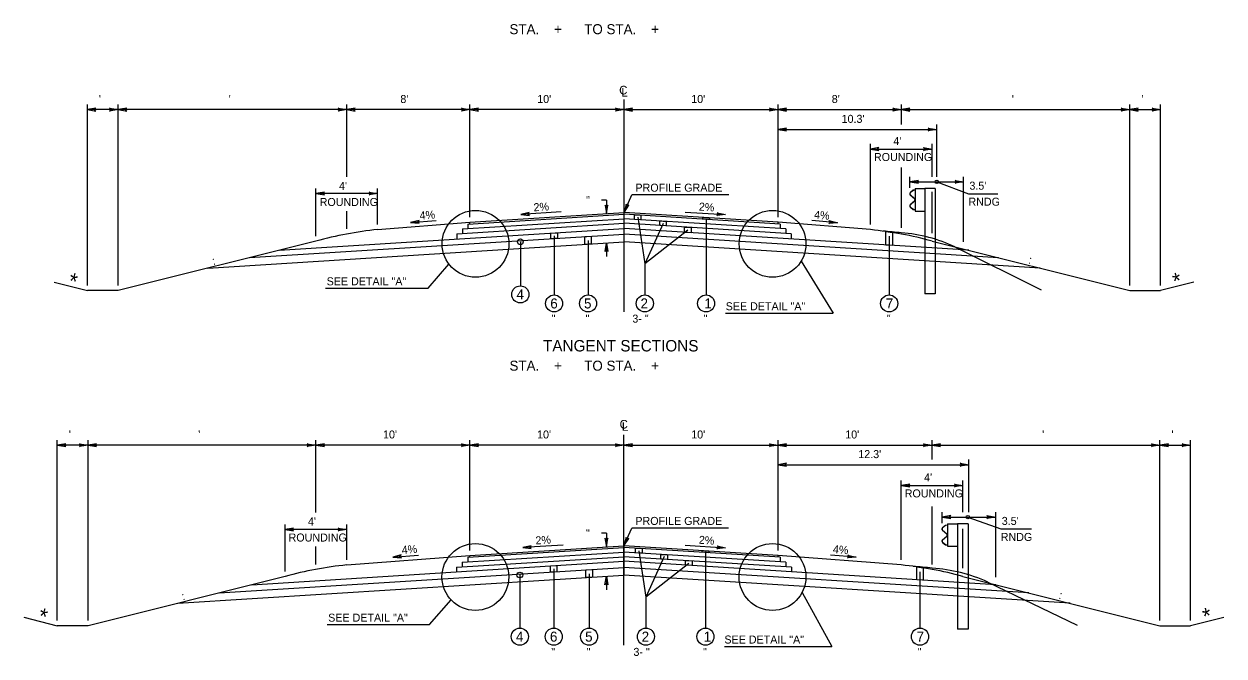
# Model space of a CAD drawing. Extents: x -540 to 1231, y -564 to 421.
# Drawn here: x -378.4 to -168.6, y -301.4 to -190.9 of the extents above; entities that cross this region are included whole.
import ezdxf

# ---------------------------------------------------------------- set-up
doc = ezdxf.new("R2010")
doc.units = 0
doc.layers.add('1', color=7, linetype='Continuous')
doc.layers.add('Des_ Drain_ Ftrs', color=7, linetype='Continuous')

msp = doc.modelspace()

# ---------------------------------------------------------------- linework, layer by layer
at = {"layer": '1'}
for p, q in [((-367.36, -236.6), (-367.36, -204.98)), ((-361.97, -236.6), (-361.97, -204.98)), ((-322, -217.64), (-322, -204.98)), ((-300.45, -224.66), (-300.45, -204.98)), ((-273.51, -241.23), (-273.51, -204.1)), ((-246.57, -224.66), (-246.57, -204.98)), ((-225.01, -208.45), (-225.01, -204.98)), ((-185.06, -236.61), (-185.06, -204.98)), ((-179.67, -236.61), (-179.67, -204.98)), ((-361.97, -205.86), (-367.36, -205.86)), ((-322, -205.86), (-361.97, -205.86)), ((-300.45, -205.86), (-322, -205.86)), ((-273.51, -205.86), (-300.45, -205.86)), ((-273.51, -205.86), (-246.57, -205.86)), ((-246.57, -205.86), (-225.01, -205.86)), ((-225.01, -205.86), (-185.06, -205.86)), ((-185.06, -205.86), (-179.67, -205.86)), ((-246.57, -209.33), (-218.82, -209.33)), ((-218.82, -217.61), (-218.82, -208.45)), ((-230.4, -225.96), (-230.4, -211.87)), ((-219.63, -217.61), (-219.63, -211.87)), ((-361.97, -233.49), (-361.97, -212.02)), ((-230.4, -212.75), (-219.63, -212.75)), ((-225.01, -226.52), (-225.01, -215.99)), ((-223.51, -219.56), (-223.51, -217.61)), ((-214.13, -228.97), (-214.13, -217.61)), ((-327.38, -227.96), (-327.38, -219.65)), ((-316.6, -225.95), (-316.6, -219.65)), ((-223.51, -218.49), (-214.13, -218.49)), ((-222.92, -219.95), (-223.43, -220.34)), ((-222.9, -219.98), (-223.42, -220.37)), ((-222.6, -219.9), (-222.92, -219.95)), ((-222.6, -219.93), (-222.9, -219.98)), ((-222.6, -219.67), (-222.6, -223.6)), ((-222.6, -219.67), (-220.92, -219.67)), ((-220.92, -219.67), (-220.92, -238.07)), ((-219.09, -219.67), (-220.92, -219.67)), ((-219.63, -227.48), (-219.63, -220.24)), ((-219.09, -219.67), (-219.09, -238.07)), ((-218.82, -218.49), (-213.26, -220.56)), ((-316.6, -220.53), (-327.38, -220.53)), ((-276.56, -221.67), (-277.44, -221.67)), ((-276.56, -221.67), (-276.56, -224.04)), ((-273.51, -223.84), (-272.12, -220.79)), ((-255.2, -220.79), (-272.12, -220.79)), ((-223.45, -220.78), (-222.72, -221.41)), ((-222.72, -221.86), (-223.45, -222.5)), ((-223.43, -220.75), (-222.7, -221.39)), ((-222.7, -221.88), (-223.43, -222.52)), ((-222.63, -221.6), (-222.63, -221.67)), ((-222.6, -221.6), (-222.6, -221.67)), ((-213.26, -220.56), (-208.11, -220.56)), ((-322, -226.73), (-322, -223.59)), ((-300.81, -225.86), (-273.51, -224.14)), ((-300.45, -225.53), (-273.51, -223.84)), ((-284.48, -223.76), (-291.56, -224.2)), ((-246.57, -225.54), (-273.51, -223.85)), ((-246.21, -225.86), (-273.51, -224.14)), ((-262.82, -223.78), (-255.75, -224.22)), ((-223.43, -222.93), (-222.92, -223.32)), ((-223.42, -222.91), (-222.9, -223.29)), ((-222.92, -223.32), (-222.6, -223.37)), ((-222.9, -223.29), (-222.6, -223.34)), ((-222.6, -223.6), (-220.92, -223.6)), ((-316.6, -226.83), (-300.45, -225.53)), ((-310.83, -225.61), (-306.34, -225.25)), ((-302.75, -227.57), (-273.51, -225.73)), ((-301.78, -226.71), (-273.51, -224.94)), ((-300.81, -225.86), (-300.81, -226.65)), ((-300.45, -225.83), (-300.45, -225.53)), ((-245.23, -226.72), (-273.51, -224.94)), ((-244.26, -227.58), (-273.51, -225.74)), ((-271.11, -224.65), (-269.87, -232.8)), ((-266.69, -225.79), (-269.87, -232.8)), ((-259.16, -224.94), (-259.16, -238.26)), ((-230.4, -226.84), (-246.57, -225.54)), ((-246.57, -225.84), (-246.57, -225.54)), ((-246.21, -225.86), (-246.21, -226.64)), ((-236.2, -225.63), (-240.69, -225.27)), ((-338.99, -231.74), (-273.51, -227.63)), ((-333.82, -230.45), (-273.51, -226.66)), ((-302.75, -227.57), (-302.75, -228.5)), ((-301.78, -226.71), (-301.78, -227.51)), ((-285.73, -227.9), (-285.73, -238.26)), ((-279.8, -228.73), (-279.8, -238.26)), ((-213.19, -230.46), (-273.51, -226.66)), ((-208.03, -231.75), (-273.51, -227.63)), ((-262.35, -226.91), (-269.87, -232.8)), ((-245.23, -226.72), (-245.23, -227.51)), ((-244.26, -227.58), (-244.26, -228.5)), ((-227.14, -228), (-227.14, -238.26)), ((-223.51, -227.62), (-223.51, -227.62)), ((-327.38, -228.84), (-361.97, -237.48)), ((-346.28, -233.56), (-273.51, -228.99)), ((-291.64, -228.96), (-291.64, -236.67)), ((-276.56, -229.19), (-276.56, -231.56)), ((-200.74, -233.57), (-273.51, -228.99)), ((-219.63, -228.85), (-185.06, -237.49)), ((-215.63, -229.85), (-200.58, -237.38)), ((-307.76, -237.08), (-304.12, -232.86)), ((-269.87, -232.8), (-269.87, -238.26)), ((-242.55, -232.36), (-236.96, -241.44)), ((-373.18, -236.02), (-367.36, -237.48)), ((-325.7, -237.08), (-307.76, -237.08)), ((-173.84, -236.03), (-179.67, -237.49)), ((-361.97, -237.48), (-367.36, -237.48)), ((-219.09, -238.07), (-220.92, -238.07)), ((-185.06, -237.49), (-179.67, -237.49)), ((-255.74, -241.44), (-236.96, -241.44)), ((-372.61, -295.19), (-372.61, -263.62)), ((-367.22, -295.19), (-367.22, -263.62)), ((-327.4, -276.28), (-327.4, -263.62)), ((-300.46, -282.91), (-300.46, -263.62)), ((-273.52, -299.47), (-273.52, -262.74)), ((-246.58, -282.91), (-246.58, -263.62)), ((-219.64, -267.05), (-219.64, -263.62)), ((-179.8, -295.19), (-179.8, -263.62)), ((-174.42, -295.19), (-174.42, -263.62)), ((-367.22, -264.5), (-372.61, -264.5)), ((-327.4, -264.5), (-367.22, -264.5)), ((-300.46, -264.5), (-327.4, -264.5)), ((-273.52, -264.5), (-300.46, -264.5)), ((-273.52, -264.5), (-246.58, -264.5)), ((-246.58, -264.5), (-219.64, -264.5)), ((-219.64, -264.5), (-179.8, -264.5)), ((-179.8, -264.5), (-174.42, -264.5)), ((-246.58, -267.93), (-213.21, -267.93)), ((-213.21, -276.21), (-213.21, -267.05)), ((-225.03, -284.58), (-225.03, -270.67)), ((-214.25, -276.21), (-214.25, -270.67)), ((-225.03, -271.55), (-214.25, -271.55)), ((-219.64, -285.35), (-219.64, -275.21)), ((-217.9, -278.16), (-217.9, -276.21)), ((-208.51, -287.57), (-208.51, -276.21)), ((-332.78, -286.58), (-332.78, -278.38)), ((-322, -284.57), (-322, -278.38)), ((-273.52, -282.09), (-272.13, -279.04)), ((-255.22, -279.04), (-272.13, -279.04)), ((-217.9, -277.09), (-208.51, -277.09)), ((-217.28, -278.55), (-217.82, -278.94)), ((-217.27, -278.58), (-217.8, -278.97)), ((-216.95, -278.5), (-217.28, -278.55)), ((-216.95, -278.53), (-217.27, -278.58)), ((-216.95, -278.27), (-216.95, -282.2)), ((-216.95, -278.27), (-215.2, -278.27)), ((-215.2, -278.27), (-215.2, -296.67)), ((-213.31, -278.27), (-215.2, -278.27)), ((-213.38, -277.09), (-207.62, -279.16)), ((-213.31, -278.27), (-213.31, -296.67)), ((-322, -279.26), (-332.78, -279.26)), ((-276.59, -279.92), (-277.47, -279.92)), ((-276.59, -279.92), (-276.59, -282.28)), ((-217.83, -279.37), (-217.07, -280.01)), ((-217.07, -280.46), (-217.83, -281.1)), ((-217.81, -279.35), (-217.05, -279.99)), ((-217.05, -280.48), (-217.81, -281.12)), ((-216.98, -280.2), (-216.98, -280.27)), ((-216.95, -280.2), (-216.95, -280.27)), ((-214.25, -286.03), (-214.25, -279.15)), ((-207.62, -279.16), (-202.27, -279.16)), ((-327.4, -285.35), (-327.4, -282.23)), ((-301.82, -284.98), (-273.52, -283.2)), ((-300.83, -284.11), (-273.52, -282.39)), ((-300.47, -283.79), (-273.52, -282.09)), ((-284.14, -281.99), (-291.22, -282.43)), ((-273.52, -282.09), (-273.52, -282.39)), ((-246.58, -283.79), (-273.52, -282.09)), ((-273.52, -282.39), (-273.52, -283.2)), ((-246.21, -284.11), (-273.52, -282.39)), ((-273.52, -283.2), (-273.52, -284.01)), ((-245.22, -284.98), (-273.52, -283.2)), ((-270.91, -282.97), (-269.68, -291.06)), ((-262.82, -282.01), (-255.75, -282.45)), ((-259.27, -283.17), (-259.27, -296.5)), ((-217.82, -281.53), (-217.28, -281.92)), ((-217.8, -281.5), (-217.27, -281.89)), ((-217.28, -281.92), (-216.95, -281.97)), ((-217.27, -281.89), (-216.95, -281.94)), ((-216.95, -282.2), (-215.2, -282.2)), ((-338.57, -288.91), (-273.52, -284.82)), ((-322, -285.45), (-300.47, -283.79)), ((-313.96, -284.07), (-309.47, -283.73)), ((-302.81, -285.85), (-273.52, -284.01)), ((-301.82, -284.98), (-301.82, -285.79)), ((-300.83, -284.11), (-300.83, -284.92)), ((-300.47, -284.09), (-300.47, -283.79)), ((-273.52, -284.01), (-273.52, -284.82)), ((-244.24, -285.85), (-273.52, -284.01)), ((-273.52, -284.82), (-273.52, -285.9)), ((-208.46, -288.91), (-273.52, -284.82)), ((-266.48, -284), (-269.68, -291.06)), ((-262.19, -285.2), (-269.68, -291.06)), ((-225.03, -285.46), (-246.58, -283.79)), ((-246.58, -284.09), (-246.58, -283.79)), ((-246.21, -284.11), (-246.21, -284.92)), ((-245.22, -284.98), (-245.22, -285.8)), ((-232.91, -284.08), (-237.39, -283.73)), ((-332.78, -287.46), (-367.22, -296.07)), ((-351.54, -292.15), (-273.52, -287.25)), ((-344.33, -290.35), (-273.52, -285.9)), ((-302.81, -285.85), (-302.81, -286.66)), ((-291.73, -287.21), (-291.73, -296.5)), ((-285.8, -286.16), (-285.8, -296.5)), ((-279.62, -287.01), (-279.62, -296.5)), ((-276.59, -287.44), (-276.59, -289.81)), ((-273.52, -285.9), (-273.52, -287.25)), ((-202.69, -290.35), (-273.52, -285.9)), ((-195.49, -292.15), (-273.52, -287.25)), ((-244.24, -285.85), (-244.24, -286.67)), ((-221.75, -286.63), (-221.75, -296.5)), ((-217.9, -286.22), (-217.9, -286.22)), ((-214.25, -287.46), (-179.8, -296.07)), ((-209.9, -288.45), (-194.28, -295.98)), ((-307.5, -295.88), (-303.76, -291.56)), ((-269.68, -291.06), (-269.68, -296.5)), ((-242.37, -290.27), (-237.17, -299.7)), ((-378.44, -294.61), (-372.61, -296.07)), ((-325.43, -295.88), (-307.5, -295.88)), ((-168.59, -294.62), (-174.42, -296.07)), ((-367.22, -296.07), (-372.61, -296.07)), ((-213.31, -296.67), (-215.2, -296.67)), ((-179.8, -296.07), (-174.42, -296.07)), ((-255.96, -299.7), (-237.17, -299.7))]:
    msp.add_line(p, q, dxfattribs=at)
for points in [[(-271.69, -224.26), (-270.54, -224.33), (-270.54, -225.13), (-271.69, -225.05)], [(-267.27, -225.33), (-266.12, -225.4), (-266.12, -226.2), (-267.27, -226.13)], [(-262.92, -226.4), (-261.78, -226.47), (-261.78, -227.4), (-262.92, -227.33)], [(-259.73, -224.71), (-258.58, -224.79), (-258.58, -225.08), (-259.73, -225.01)], [(-286.31, -227.47), (-285.16, -227.39), (-285.16, -228.36), (-286.31, -228.43)], [(-280.38, -228.06), (-279.23, -227.99), (-279.23, -229.35), (-280.38, -229.42)], [(-227.72, -227.17), (-226.57, -227.35), (-226.57, -229.62), (-227.72, -229.54)], [(-271.48, -282.52), (-270.34, -282.59), (-270.34, -283.4), (-271.48, -283.33)], [(-259.84, -282.95), (-258.7, -283.02), (-258.7, -283.32), (-259.84, -283.25)], [(-267.05, -283.61), (-265.9, -283.68), (-265.9, -284.49), (-267.05, -284.42)], [(-262.77, -284.69), (-261.62, -284.76), (-261.62, -285.57), (-262.77, -285.5)], [(-286.37, -285.63), (-285.23, -285.55), (-285.23, -286.63), (-286.37, -286.71)], [(-280.19, -286.32), (-279.04, -286.25), (-279.04, -287.59), (-280.19, -287.67)], [(-222.32, -285.79), (-221.17, -285.96), (-221.17, -288.11), (-222.32, -288.04)]]:
    msp.add_lwpolyline(points, close=True, dxfattribs=at)
for centre, radius in [((-218.82, -218.49), 0.3), ((-299.49, -229.32), 5.84), ((-247.53, -229.32), 5.84), ((-291.64, -228.96), 0.5), ((-291.64, -238.16), 1.49), ((-285.73, -239.74), 1.49), ((-279.8, -239.74), 1.49), ((-269.87, -239.74), 1.49), ((-259.16, -239.74), 1.49), ((-227.14, -239.74), 1.49), ((-299.5, -287.56), 5.84), ((-247.54, -287.56), 5.84), ((-291.73, -287.21), 0.5), ((-291.73, -297.99), 1.49), ((-285.8, -297.99), 1.49), ((-279.62, -297.99), 1.49), ((-269.68, -297.99), 1.49), ((-259.27, -297.99), 1.49), ((-221.75, -297.99), 1.49)]:
    msp.add_circle(centre, radius, dxfattribs=at)
for centre, radius, start, end in [((-223.27, -220.57), 0.278, 126.9799, 229.021), ((-223.27, -220.57), 0.249, 126.9799, 229.021), ((-222.88, -221.6), 0.249, 0, 49.0365), ((-222.88, -221.67), 0.249, 310.9635, 0), ((-222.88, -221.6), 0.278, 0, 49.0365), ((-222.88, -221.67), 0.278, 310.9635, 0), ((-223.27, -222.71), 0.278, 130.979, 233.0201), ((-223.27, -222.71), 0.249, 130.979, 233.0201), ((-309.72, -293.67), 67.19, 95.8795, 105.2381), ((-237.29, -293.68), 67.19, 74.7619, 84.1205), ((-235.84, -328.06), 101.24, 83.8633, 85.6775), ((-227.14, -254.68), 27.37, 65.1374, 85.5513), ((-315.12, -352.29), 67.19, 95.8795, 105.2381), ((-231.91, -352.29), 67.19, 74.7598, 84.1183)]:
    msp.add_arc(centre, radius, start, end, dxfattribs=at)
msp.add_ellipse((-213.38, -277.09), major_axis=(-0.311, 0), ratio=0.964041, dxfattribs=at)
for centre, major_axis, start_param, end_param in [((-217.64, -279.16), (-0.288, 0), 5.35781, 7.138763), ((-217.64, -279.16), (-0.258, 0), 5.35781, 7.138763), ((-217.64, -281.31), (-0.288, 0), 5.427608, 7.208561), ((-217.64, -281.31), (-0.258, 0), 5.427608, 7.208561), ((-217.24, -280.2), (0.258, 0), 0, 0.855848), ((-217.24, -280.27), (0.258, 0), 5.427337, 6.283185), ((-217.24, -280.2), (0.288, 0), 0, 0.855848), ((-217.24, -280.27), (0.288, 0), 5.427337, 6.283185), ((-230.86, -386.66), (105.02, 0), 1.463691, 1.495354), ((-221.83, -313.28), (28.39, 0), 1.136862, 1.493152)]:
    msp.add_ellipse(centre, major_axis=major_axis, ratio=0.964041, start_param=start_param, end_param=end_param, dxfattribs=at)
at = {"layer": 'Des_ Drain_ Ftrs'}
for points in [[(-367.36, -205.86), (-365.87, -206.11), (-366.16, -205.86), (-365.87, -205.62)], [(-361.97, -205.86), (-363.46, -206.11), (-363.16, -205.86), (-363.46, -205.62)], [(-361.97, -205.86), (-360.48, -206.11), (-360.77, -205.86), (-360.48, -205.62)], [(-322, -205.86), (-323.49, -206.11), (-323.2, -205.86), (-323.49, -205.62)], [(-322, -205.86), (-320.52, -206.11), (-320.81, -205.86), (-320.52, -205.62)], [(-300.45, -205.86), (-301.94, -206.11), (-301.64, -205.86), (-301.94, -205.62)], [(-300.45, -205.86), (-298.96, -206.11), (-299.26, -205.86), (-298.96, -205.62)], [(-273.51, -205.86), (-275, -206.11), (-274.7, -205.86), (-275, -205.62)], [(-273.51, -205.86), (-272.02, -206.11), (-272.32, -205.86), (-272.02, -205.62)], [(-246.57, -205.86), (-248.06, -206.11), (-247.76, -205.86), (-248.06, -205.62)], [(-246.57, -205.86), (-245.08, -206.11), (-245.37, -205.86), (-245.08, -205.62)], [(-225.01, -205.86), (-226.5, -206.11), (-226.21, -205.86), (-226.5, -205.62)], [(-225.01, -205.86), (-223.53, -206.11), (-223.82, -205.86), (-223.53, -205.62)], [(-185.06, -205.86), (-186.55, -206.11), (-186.25, -205.86), (-186.55, -205.62)], [(-185.06, -205.86), (-183.57, -206.11), (-183.86, -205.86), (-183.57, -205.62)], [(-179.67, -205.86), (-181.16, -206.11), (-180.86, -205.86), (-181.16, -205.62)], [(-246.57, -209.33), (-245.08, -209.58), (-245.38, -209.33), (-245.08, -209.08)], [(-218.82, -209.33), (-220.31, -209.58), (-220.02, -209.33), (-220.31, -209.08)], [(-230.4, -212.75), (-228.92, -213), (-229.21, -212.75), (-228.92, -212.5)], [(-219.63, -212.75), (-221.12, -213), (-220.82, -212.75), (-221.12, -212.5)], [(-223.51, -218.49), (-222.03, -218.73), (-222.32, -218.49), (-222.03, -218.24)], [(-214.13, -218.49), (-215.62, -218.73), (-215.32, -218.49), (-215.62, -218.24)], [(-327.38, -220.53), (-325.89, -220.78), (-326.19, -220.53), (-325.89, -220.28)], [(-316.6, -220.53), (-318.09, -220.78), (-317.8, -220.53), (-318.09, -220.28)], [(-273.51, -223.84), (-272.67, -222.59), (-273.02, -222.76), (-273.12, -222.39)], [(-291.56, -224.2), (-290.06, -224.36), (-290.37, -224.13), (-290.09, -223.86)], [(-276.56, -224.04), (-276.32, -222.55), (-276.56, -222.84), (-276.81, -222.55)], [(-255.75, -224.22), (-257.25, -224.38), (-256.94, -224.15), (-257.22, -223.88)], [(-310.83, -225.61), (-309.32, -225.74), (-309.64, -225.52), (-309.36, -225.25)], [(-236.2, -225.63), (-237.71, -225.76), (-237.39, -225.53), (-237.67, -225.26)], [(-276.56, -229.19), (-276.32, -230.68), (-276.56, -230.38), (-276.81, -230.68)], [(-372.61, -264.5), (-371.12, -264.75), (-371.42, -264.5), (-371.12, -264.26)], [(-367.22, -264.5), (-368.71, -264.75), (-368.41, -264.5), (-368.71, -264.26)], [(-367.22, -264.5), (-365.73, -264.75), (-366.03, -264.5), (-365.73, -264.26)], [(-327.4, -264.5), (-328.89, -264.75), (-328.6, -264.5), (-328.89, -264.26)], [(-327.4, -264.5), (-325.91, -264.75), (-326.21, -264.5), (-325.91, -264.26)], [(-300.46, -264.5), (-301.95, -264.75), (-301.65, -264.5), (-301.95, -264.26)], [(-300.46, -264.5), (-298.97, -264.75), (-299.27, -264.5), (-298.97, -264.26)], [(-273.52, -264.5), (-275.01, -264.75), (-274.71, -264.5), (-275.01, -264.26)], [(-273.52, -264.5), (-272.03, -264.75), (-272.33, -264.5), (-272.03, -264.26)], [(-246.58, -264.5), (-248.07, -264.75), (-247.77, -264.5), (-248.07, -264.26)], [(-246.58, -264.5), (-245.09, -264.75), (-245.39, -264.5), (-245.09, -264.26)], [(-219.64, -264.5), (-221.13, -264.75), (-220.83, -264.5), (-221.13, -264.26)], [(-219.64, -264.5), (-218.15, -264.75), (-218.44, -264.5), (-218.15, -264.26)], [(-179.8, -264.5), (-181.29, -264.75), (-181, -264.5), (-181.29, -264.26)], [(-179.8, -264.5), (-178.32, -264.75), (-178.61, -264.5), (-178.32, -264.26)], [(-174.42, -264.5), (-175.9, -264.75), (-175.61, -264.5), (-175.9, -264.26)], [(-246.58, -267.93), (-245.09, -268.18), (-245.38, -267.93), (-245.09, -267.68)], [(-213.21, -267.93), (-214.7, -268.18), (-214.4, -267.93), (-214.7, -267.68)], [(-225.03, -271.55), (-223.54, -271.8), (-223.83, -271.55), (-223.54, -271.31)], [(-214.25, -271.55), (-215.74, -271.8), (-215.44, -271.55), (-215.74, -271.31)], [(-217.9, -277.09), (-216.36, -277.33), (-216.66, -277.09), (-216.36, -276.84)], [(-208.51, -277.09), (-210.06, -277.33), (-209.75, -277.09), (-210.06, -276.84)], [(-332.78, -279.26), (-331.29, -279.51), (-331.59, -279.26), (-331.29, -279.01)], [(-322, -279.26), (-323.49, -279.51), (-323.2, -279.26), (-323.49, -279.01)], [(-276.59, -282.28), (-276.34, -280.8), (-276.59, -281.09), (-276.84, -280.8)], [(-273.52, -282.09), (-272.68, -280.84), (-273.03, -281.01), (-273.13, -280.63)], [(-291.22, -282.43), (-289.72, -282.59), (-290.03, -282.36), (-289.75, -282.09)], [(-255.75, -282.45), (-257.25, -282.61), (-256.94, -282.38), (-257.22, -282.11)], [(-313.96, -284.07), (-312.45, -284.21), (-312.77, -283.98), (-312.49, -283.71)], [(-232.91, -284.08), (-234.41, -284.22), (-234.1, -283.99), (-234.37, -283.72)], [(-276.59, -287.44), (-276.34, -288.93), (-276.59, -288.63), (-276.84, -288.93)]]:
    msp.add_lwpolyline(points, close=True, dxfattribs=at)

# ---------------------------------------------------------------- texts
at = {"layer": '1'}
for s, height, p in [('STA.    +      TO STA.    +     ', 1.75, (-293.54, -192.68)), (" '", 1.4, (-365.86, -204.71)), ("  '", 1.4, (-343.68, -204.71)), ("8'", 1.4, (-312.62, -204.71)), ("10'", 1.4, (-288.69, -204.71)), ("10'", 1.4, (-261.75, -204.71)), ("8'", 1.4, (-237.18, -204.71)), ("  '", 1.4, (-206.73, -204.71)), (" '", 1.4, (-183.56, -204.71)), ("10.3'", 1.4, (-235.46, -208.18)), ("4'", 1.4, (-226.41, -212.05)), ('ROUNDING', 1.4, (-229.8, -214.85)), ("4'", 1.4, (-323.35, -219.91)), ('PROFILE GRADE', 1.4, (-271.51, -220.21)), ("3.5'", 1.4, (-213.11, -219.86)), ('ROUNDING', 1.4, (-326.73, -222.71)), ('RNDG', 1.4, (-213.28, -222.66)), ('SEE DETAIL "A"', 1.4, (-325.51, -236.58)), ('4', 1.75, (-292.31, -239.03)), ('6', 1.75, (-286.4, -240.62)), ('5', 1.75, (-280.5, -240.62)), ('2', 1.75, (-270.62, -240.62)), ('1', 1.75, (-259.46, -240.62)), ('7', 1.75, (-227.73, -240.62)), ('SEE DETAIL "A"', 1.4, (-255.73, -240.94)), (' "', 1.4, (-286.68, -243.1)), (' "', 1.4, (-280.75, -243.1)), ('3- "', 1.4, (-272.05, -243.1)), (' "', 1.4, (-260.1, -243.1)), ('  "', 1.4, (-228.59, -243.1)), ('TANGENT SECTIONS', 2, (-287.68, -248.14)), ('STA.    +      TO STA.    +     ', 1.75, (-293.54, -251.5)), (" '", 1.4, (-371.11, -263.35)), ("  '", 1.4, (-349.01, -263.35)), ("10'", 1.4, (-315.65, -263.35)), ("10'", 1.4, (-288.71, -263.35)), ("10'", 1.4, (-261.76, -263.35)), ("10'", 1.4, (-234.82, -263.35)), ("  '", 1.4, (-201.42, -263.35)), (" '", 1.4, (-178.3, -263.35)), ("12.3'", 1.4, (-232.54, -266.78)), ("4'", 1.4, (-221.03, -270.85)), ('ROUNDING', 1.4, (-224.42, -273.65)), ("4'", 1.4, (-328.78, -278.56)), ('PROFILE GRADE', 1.4, (-271.52, -278.46)), ("3.5'", 1.4, (-207.45, -278.46)), ('ROUNDING', 1.4, (-332.17, -281.36)), ('RNDG', 1.4, (-207.63, -281.26)), ('SEE DETAIL "A"', 1.4, (-325.24, -295.37)), ('4', 1.75, (-292.41, -298.86)), ('6', 1.75, (-286.46, -298.86)), ('5', 1.75, (-280.31, -298.86)), ('2', 1.75, (-270.42, -298.86)), ('1', 1.75, (-259.57, -298.86)), ('SEE DETAIL "A"', 1.4, (-255.95, -299.19)), ('7', 1.75, (-222.34, -298.86)), (' "', 1.4, (-286.74, -301.35)), (' "', 1.4, (-280.56, -301.35)), ('3- "', 1.4, (-271.86, -301.35)), (' "', 1.4, (-260.21, -301.35)), ('  "', 1.4, (-223.19, -301.35))]:
    msp.add_text(s, height=height, dxfattribs=at).set_placement(p)
for s, height, rotation, p in [('2%', 1.4, 3.7235, (-289.29, -223.65)), ('  "', 1.4, 0.1438, (-281.18, -222.37)), ('2%', 1.4, 356.2763, (-260.46, -223.5)), ('4%', 1.4, 4.8702, (-309.2, -225.1)), ('4%', 1.4, 355.1224, (-240.32, -224.9)), (' : ', 1.4, 14.2282, (-345.85, -233.17)), (' : ', 1.4, 345.7718, (-203.39, -232.62)), ('*', 2.8, 347.1521, (-370.87, -237.05)), ('*', 2.8, 12.8479, (-177.21, -237.3)), ('2%', 1.4, 3.7237, (-288.95, -281.88)), ('  "', 1.4, 0.1438, (-281.2, -280.62)), ('2%', 1.4, 356.2769, (-260.46, -281.74)), ('4%', 1.4, 4.7057, (-312.33, -283.56)), ('4%', 1.4, 355.2889, (-237.02, -283.37)), (' : ', 1.4, 14.2282, (-351.18, -291.78)), (' : ', 1.4, 345.7718, (-198.08, -291.22)), ('*', 2.8, 347.1521, (-376.12, -295.64)), ('*', 2.8, 12.8479, (-171.95, -295.88))]:
    msp.add_text(s, height=height, rotation=rotation, dxfattribs=at).set_placement(p)
at = {"layer": 'Des_ Drain_ Ftrs'}
for s, p in [('C', (-274.36, -203.21)), ('L', (-273.96, -203.61)), ('C', (-274.28, -261.61)), ('L', (-273.89, -262.01))]:
    msp.add_text(s, height=1.5, dxfattribs=at).set_placement(p)

doc.saveas('drawing.dxf')
